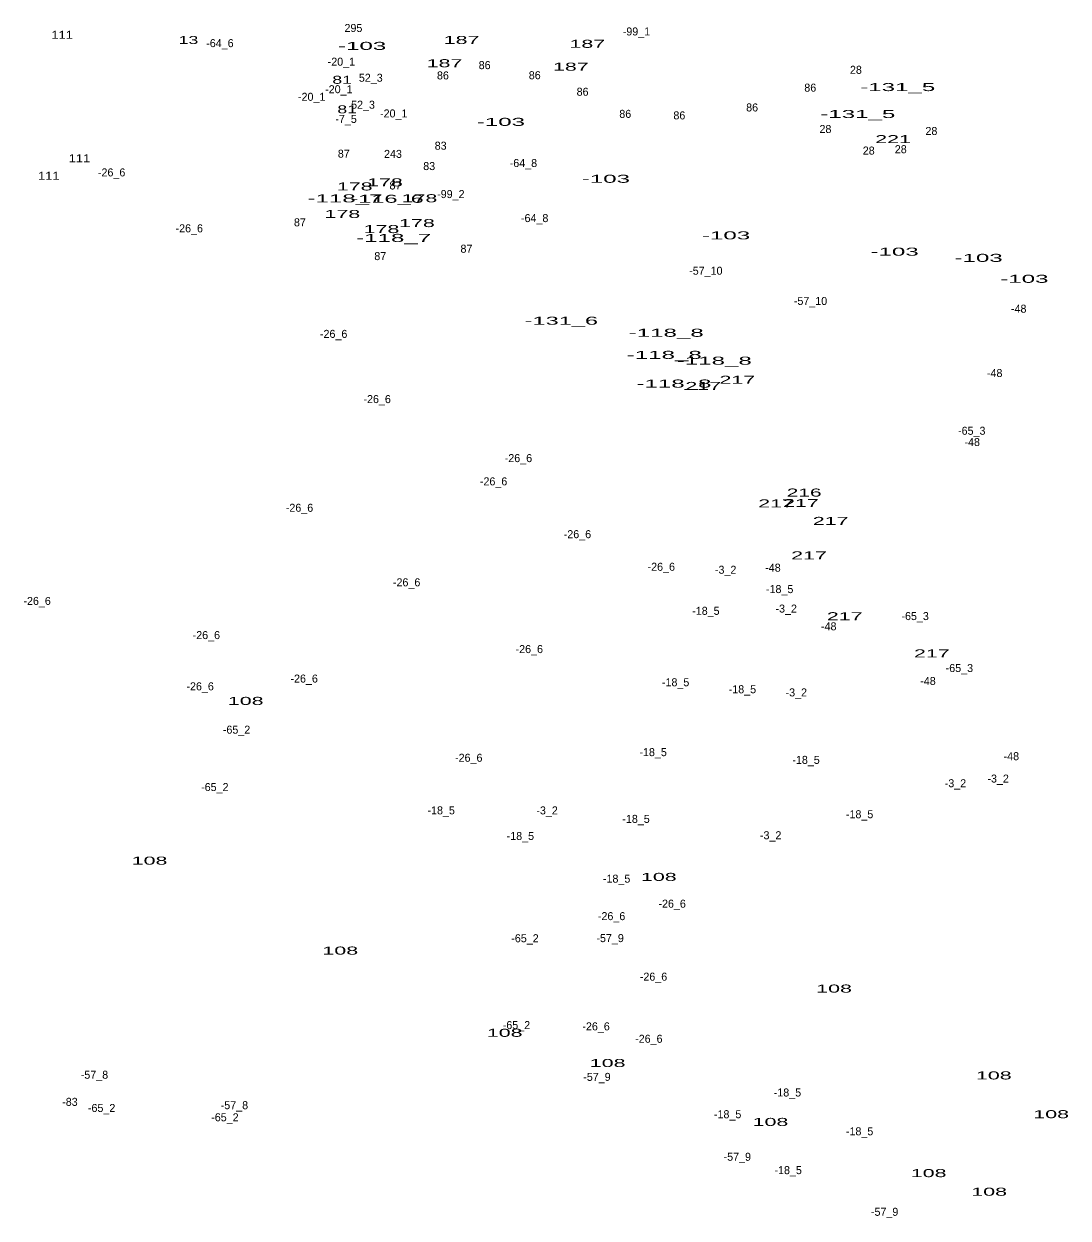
# Model space of a CAD drawing. Extents: x -656096 to -652763, y -1002270 to -998958.
# Drawn here: x -654060 to -653538, y -1002208 to -1001611 of the extents above; entities that cross this region are included whole.
import ezdxf
from ezdxf.enums import TextEntityAlignment as Align

# ---------------------------------------------------------------- set-up
doc = ezdxf.new("R2010")
doc.units = 0
doc.header["$LTSCALE"] = 1.6
doc.layers.add('24', color=7, linetype='Continuous')

msp = doc.modelspace()

# ---------------------------------------------------------------- texts
at = {"layer": '24'}
for s, p in [('295', (-653894.953, -1001614.97)), ('-99_1', (-653753.597, -1001616.69)), ('-64_6', (-653961.628, -1001622.53)), ('-20_1', (-653900.97, -1001631.79)), ('86', (-653829.413, -1001633.52)), ('52_3', (-653886.285, -1001639.82)), ('86', (-653850.253, -1001638.66)), ('86', (-653804.403, -1001638.57)), ('28', (-653643.987, -1001635.86)), ('-20_1', (-653902.23, -1001645.56)), ('86', (-653780.503, -1001646.81)), ('86', (-653666.783, -1001644.77)), ('-20_1', (-653915.8, -1001649.34)), ('52_3', (-653890.165, -1001653.3)), ('-20_1', (-653874.82, -1001657.66)), ('86', (-653759.183, -1001657.87)), ('86', (-653732.163, -1001658.63)), ('86', (-653695.823, -1001654.66)), ('-7_5', (-653898.619, -1001660.4)), ('28', (-653659.197, -1001665.44)), ('28', (-653606.277, -1001666.41)), ('83', (-653851.387, -1001673.77)), ('28', (-653637.587, -1001676.2)), ('28', (-653621.587, -1001675.53)), ('87', (-653899.763, -1001677.74)), ('243', (-653875.201, -1001677.87)), ('-64_8', (-653810.052, -1001682.44)), ('-26_6', (-654015.713, -1001687.12)), ('83', (-653857.107, -1001683.95)), ('87', (-653873.983, -1001693.64)), ('-99_2', (-653846.293, -1001697.94)), ('87', (-653921.673, -1001712.06)), ('-64_8', (-653804.432, -1001709.94)), ('-26_6', (-653976.943, -1001715.05)), ('87', (-653881.543, -1001728.94)), ('87', (-653838.503, -1001725.25)), ('-57_10', (-653718.936, -1001736.24)), ('-57_10', (-653666.656, -1001751.35)), ('-48', (-653562.669, -1001755.22)), ('-26_6', (-653904.823, -1001767.8)), ('-48', (-653574.669, -1001787.37)), ('-26_6', (-653883.103, -1001800.38)), ('-65_3', (-653586.128, -1001816.2)), ('-48', (-653585.899, -1001821.85)), ('-26_6', (-653812.543, -1001829.86)), ('-26_6', (-653824.943, -1001841.49)), ('-26_6', (-653921.883, -1001854.68)), ('-26_6', (-653783.073, -1001867.87)), ('-26_6', (-653741.193, -1001884.16)), ('-3_2', (-653709.043, -1001885.65)), ('-48', (-653685.429, -1001884.61)), ('-26_6', (-653868.373, -1001891.92)), ('-18_5', (-653682.066, -1001895.31)), ('-26_6', (-654052.933, -1001901.23)), ('-18_5', (-653718.906, -1001906.17)), ('-3_2', (-653678.803, -1001905.04)), ('-65_3', (-653614.398, -1001908.79)), ('-48', (-653657.549, -1001913.91)), ('-26_6', (-653968.413, -1001918.29)), ('-26_6', (-653807.113, -1001925.28)), ('-65_3', (-653592.318, -1001934.75)), ('-26_6', (-653971.513, -1001943.89)), ('-26_6', (-653919.553, -1001940.02)), ('-18_5', (-653734.026, -1001941.86)), ('-18_5', (-653700.676, -1001945.35)), ('-48', (-653607.979, -1001941.22)), ('-3_2', (-653673.763, -1001946.93)), ('-65_2', (-653953.328, -1001965.55)), ('-26_6', (-653837.353, -1001979.58)), ('-18_5', (-653745.266, -1001976.77)), ('-18_5', (-653668.886, -1001980.65)), ('-48', (-653566.349, -1001978.8)), ('-3_2', (-653594.273, -1001992.32)), ('-3_2', (-653572.953, -1001989.99)), ('-65_2', (-653964.178, -1001994.22)), ('-18_5', (-653851.116, -1002005.86)), ('-3_2', (-653798.223, -1002005.89)), ('-18_5', (-653753.796, -1002010.13)), ('-18_5', (-653642.136, -1002007.8)), ('-18_5', (-653811.576, -1002018.66)), ('-3_2', (-653686.563, -1002018.3)), ('-18_5', (-653763.496, -1002039.99)), ('-26_6', (-653735.773, -1002052.5)), ('-26_6', (-653766.013, -1002058.71)), ('-65_2', (-653809.268, -1002069.76)), ('-57_9', (-653766.744, -1002069.69)), ('-26_6', (-653745.073, -1002088.96)), ('-65_2', (-653813.528, -1002113.15)), ('-26_6', (-653773.763, -1002113.79)), ('-26_6', (-653747.403, -1002119.99)), ('-57_8', (-654024.288, -1002137.97)), ('-57_9', (-653773.324, -1002139.03)), ('-18_5', (-653678.186, -1002146.83)), ('-83', (-654036.545, -1002151.5)), ('-57_8', (-653954.388, -1002153.18)), ('-65_2', (-654020.718, -1002154.56)), ('-65_2', (-653959.138, -1002159.21)), ('-18_5', (-653708.046, -1002157.69)), ('-18_5', (-653642.136, -1002166.22)), ('-57_9', (-653703.234, -1002178.94)), ('-18_5', (-653677.806, -1002185.62)), ('-57_9', (-653629.654, -1002206.44))]:
    msp.add_text(s, height=4, dxfattribs=at).set_placement(p, align=Align.CENTER)
for s, width, p in [('111', 1.2, (-654040.42, -1001618.37)), ('13', 1.65, (-653977.327, -1001620.96)), ('187', 2, (-653840.943, -1001620.94)), ('187', 2, (-653778.133, -1001622.87)), ('-103', 2.25, (-653890.607, -1001623.91)), ('187', 2, (-653849.463, -1001632.56)), ('187', 2, (-653786.363, -1001634.3)), ('81', 1.65, (-653900.587, -1001640.85)), ('-131_5', 2.25, (-653623.097, -1001644.48)), ('81', 1.65, (-653898.067, -1001655.6)), ('-131_5', 2.25, (-653643.037, -1001657.94)), ('-103', 2.25, (-653821.287, -1001661.87)), ('221', 2, (-653625.427, -1001670.49)), ('111', 1.2, (-654031.8, -1001680.06)), ('111', 1.2, (-654047.09, -1001688.78)), ('178', 2, (-653894.303, -1001694.12)), ('178', 2, (-653879.193, -1001692.09)), ('-103', 2.25, (-653768.857, -1001690.3)), ('-118_7', 2.25, (-653899.153, -1001700.09)), ('-116_6', 2.2, (-653878.157, -1001700.29)), ('178', 2, (-653861.963, -1001700.03)), ('178', 2, (-653900.473, -1001707.88)), ('178', 2, (-653863.223, -1001712.43)), ('178', 2, (-653880.943, -1001715.43)), ('-103', 2.25, (-653708.837, -1001718.58)), ('-118_7', 2.25, (-653874.853, -1001719.85)), ('-103', 2.25, (-653624.657, -1001726.72)), ('-103', 2.25, (-653582.697, -1001729.82)), ('-103', 2.25, (-653559.847, -1001740.28)), ('-131_6', 2.2, (-653791.093, -1001761.22)), ('-118_8', 2.25, (-653738.727, -1001767.24)), ('-118_8', 2.25, (-653739.697, -1001778.28)), ('-118_8', 2.25, (-653714.717, -1001781.19)), ('-118_8', 2.25, (-653734.857, -1001792.62)), ('217', 2, (-653720.243, -1001793.81)), ('217', 2, (-653703.203, -1001790.71)), ('216', 1.95, (-653669.823, -1001847.08)), ('217', 2, (-653683.843, -1001852.5)), ('217', 2, (-653671.453, -1001852.31)), ('217', 2, (-653656.603, -1001861.25)), ('217', 2, (-653667.383, -1001878.46)), ('217', 2, (-653649.573, -1001908.87)), ('217', 2, (-653606.063, -1001927.43)), ('108', 2, (-653948.754, -1001951.18)), ('108', 2, (-653996.774, -1002030.99)), ('108', 2, (-653742.424, -1002039.12)), ('108', 2, (-653901.514, -1002075.93)), ('108', 2, (-653654.894, -1002094.91)), ('108', 2, (-653819.404, -1002117)), ('108', 2, (-653767.984, -1002132.1)), ('108', 2, (-653575.124, -1002138.3)), ('108', 2, (-653546.464, -1002157.67)), ('108', 2, (-653686.654, -1002161.54)), ('108', 2, (-653607.654, -1002187.11)), ('108', 2, (-653577.444, -1002196.41))]:
    msp.add_text(s, height=4, dxfattribs=dict(at, width=width)).set_placement(p, align=Align.CENTER)

doc.saveas('drawing.dxf')
